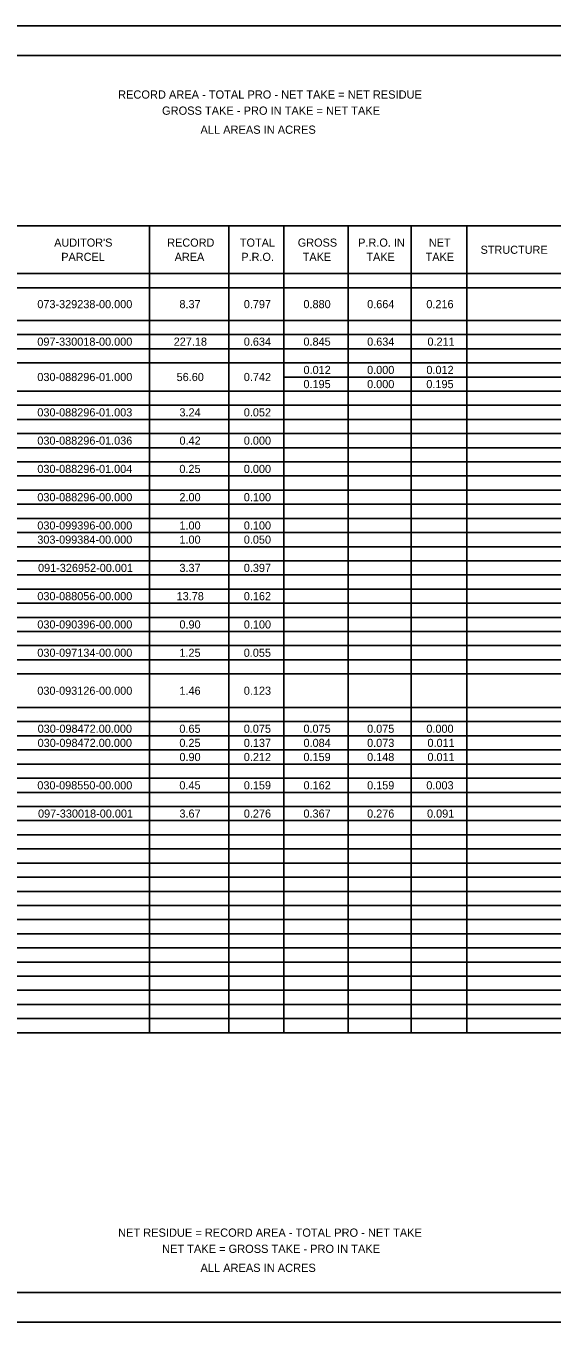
# Model space of a CAD drawing. Extents: x 0 to 38.6, y 0 to 22.
# Drawn here: x 13.07 to 22, y 0 to 22 of the extents above; entities that cross this region are included whole.
import ezdxf

# ---------------------------------------------------------------- set-up
doc = ezdxf.new("R2010")
doc.units = 0
for name, color, linetype in [('SH_Border', 7, 'Continuous'), ('SH_Cut_Line', 7, 'Continuous'), ('SH_Text', 7, 'Continuous')]:
    doc.layers.add(name, color=color, linetype=linetype)

msp = doc.modelspace()

# ---------------------------------------------------------------- linework, layer by layer
at = {"layer": 'SH_Border'}
msp.add_lwpolyline([(1.5, 21.5), (33.5, 21.5), (33.5, 0.5), (1.5, 0.5)], close=True, dxfattribs=at)
at = {"layer": 'SH_Cut_Line'}
msp.add_lwpolyline([(0, 0), (34, 0), (34, 22), (0, 22)], close=True, dxfattribs=at)
at = {"layer": 'SH_Text'}
for p, q in [((2.373, 18.606), (31.038, 18.606)), ((15.168, 18.606), (15.168, 4.911)), ((16.518, 18.606), (16.518, 4.911)), ((17.448, 18.606), (17.448, 4.911)), ((18.543, 18.606), (18.543, 4.911)), ((19.608, 18.606), (19.608, 4.911)), ((20.553, 18.606), (20.553, 4.911)), ((2.373, 17.796), (31.038, 17.796)), ((2.373, 17.556), (31.038, 17.556)), ((2.373, 17.001), (31.038, 17.001)), ((2.373, 16.761), (31.038, 16.761)), ((2.373, 16.521), (31.038, 16.521)), ((2.373, 16.281), (31.038, 16.281)), ((17.448, 16.041), (31.038, 16.041)), ((2.373, 15.801), (31.038, 15.801)), ((2.373, 15.561), (31.038, 15.561)), ((2.373, 15.321), (31.038, 15.321)), ((2.373, 15.081), (31.038, 15.081)), ((2.373, 14.841), (31.038, 14.841)), ((2.373, 14.601), (31.038, 14.601)), ((2.373, 14.361), (31.038, 14.361)), ((2.373, 14.121), (31.038, 14.121)), ((2.373, 13.881), (31.038, 13.881)), ((2.373, 13.641), (31.038, 13.641)), ((2.373, 13.401), (31.038, 13.401)), ((2.373, 13.161), (31.038, 13.161)), ((2.373, 12.921), (31.038, 12.921)), ((2.373, 12.681), (31.038, 12.681)), ((2.373, 12.441), (31.038, 12.441)), ((2.373, 12.201), (31.038, 12.201)), ((2.373, 11.961), (31.038, 11.961)), ((2.373, 11.721), (31.038, 11.721)), ((2.373, 11.481), (31.038, 11.481)), ((2.373, 11.241), (31.038, 11.241)), ((2.373, 11.001), (31.038, 11.001)), ((2.373, 10.431), (31.038, 10.431)), ((2.373, 10.191), (31.038, 10.191)), ((2.373, 9.951), (31.038, 9.951)), ((2.373, 9.711), (31.038, 9.711)), ((2.373, 9.471), (31.038, 9.471)), ((2.373, 9.231), (31.038, 9.231)), ((2.373, 8.991), (31.038, 8.991)), ((2.373, 8.751), (31.038, 8.751)), ((2.373, 8.511), (31.038, 8.511)), ((2.373, 8.271), (31.038, 8.271)), ((2.373, 8.031), (31.038, 8.031)), ((2.373, 7.791), (31.038, 7.791)), ((2.373, 7.551), (31.038, 7.551)), ((2.373, 7.311), (31.038, 7.311)), ((2.373, 7.071), (31.038, 7.071)), ((2.373, 6.831), (31.038, 6.831)), ((2.373, 6.591), (31.038, 6.591)), ((2.373, 6.351), (31.038, 6.351)), ((2.373, 6.111), (31.038, 6.111)), ((2.373, 5.871), (31.038, 5.871)), ((2.373, 5.631), (31.038, 5.631)), ((2.373, 5.391), (31.038, 5.391)), ((2.373, 5.151), (31.038, 5.151)), ((2.373, 4.911), (31.038, 4.911))]:
    msp.add_line(p, q, dxfattribs=at)

# ---------------------------------------------------------------- texts
for s, height, p in [('RECORD AREA - TOTAL PRO - NET TAKE = NET RESIDUE', 0.14, (14.637, 20.766)), ('GROSS TAKE - PRO IN TAKE = NET TAKE', 0.14, (15.383, 20.492)), ('ALL AREAS IN ACRES', 0.14, (16.035, 20.169)), ("AUDITOR'S", 0.138, (13.552, 18.253)), ('RECORD', 0.138, (15.471, 18.253)), ('TOTAL', 0.138, (16.704, 18.253)), ('GROSS', 0.138, (17.686, 18.253)), ('P.R.O. IN', 0.138, (18.711, 18.253)), ('NET', 0.138, (19.909, 18.253)), ('STRUCTURE', 0.138, (20.787, 18.132)), ('PARCEL', 0.138, (13.673, 18.011)), ('AREA', 0.138, (15.597, 18.011)), ('P.R.O.', 0.138, (16.728, 18.011)), ('TAKE', 0.138, (17.77, 18.011)), ('TAKE', 0.138, (18.85, 18.011)), ('TAKE', 0.138, (19.855, 18.011)), ('073-329238-00.000', 0.138, (13.267, 17.209)), ('8.37', 0.138, (15.678, 17.209)), ('0.797', 0.138, (16.77, 17.209)), ('0.880', 0.138, (17.782, 17.209)), ('0.664', 0.138, (18.863, 17.209)), ('0.216', 0.138, (19.867, 17.209)), ('097-330018-00.000', 0.138, (13.267, 16.572)), ('227.18', 0.138, (15.581, 16.572)), ('0.634', 0.138, (16.77, 16.572)), ('0.845', 0.138, (17.782, 16.572)), ('0.634', 0.138, (18.863, 16.572)), ('0.211', 0.138, (19.886, 16.572)), ('030-088296-01.000', 0.138, (13.267, 15.972)), ('56.60', 0.138, (15.63, 15.972)), ('0.742', 0.138, (16.77, 15.972)), ('0.012', 0.138, (17.783, 16.092)), ('0.000', 0.138, (18.862, 16.092)), ('0.012', 0.138, (19.868, 16.092)), ('0.195', 0.138, (17.782, 15.852)), ('0.000', 0.138, (18.862, 15.852)), ('0.195', 0.138, (19.867, 15.852)), ('030-088296-01.003', 0.138, (13.267, 15.372)), ('3.24', 0.138, (15.678, 15.372)), ('0.052', 0.138, (16.77, 15.372)), ('030-088296-01.036', 0.138, (13.267, 14.892)), ('0.42', 0.138, (15.679, 14.892)), ('0.000', 0.138, (16.77, 14.892)), ('030-088296-01.004', 0.138, (13.267, 14.412)), ('0.25', 0.138, (15.677, 14.412)), ('0.000', 0.138, (16.77, 14.412)), ('030-088296-00.000', 0.138, (13.267, 13.932)), ('2.00', 0.138, (15.678, 13.932)), ('0.100', 0.138, (16.77, 13.932)), ('030-099396-00.000', 0.138, (13.267, 13.452)), ('1.00', 0.138, (15.678, 13.452)), ('0.100', 0.138, (16.77, 13.452)), ('303-099384-00.000', 0.138, (13.267, 13.212)), ('1.00', 0.138, (15.678, 13.212)), ('0.050', 0.138, (16.77, 13.212)), ('091-326952-00.001', 0.138, (13.279, 12.732)), ('3.37', 0.138, (15.678, 12.732)), ('0.397', 0.138, (16.77, 12.732)), ('030-088056-00.000', 0.138, (13.267, 12.252)), ('13.78', 0.138, (15.63, 12.252)), ('0.162', 0.138, (16.77, 12.252)), ('030-090396-00.000', 0.138, (13.267, 11.772)), ('0.90', 0.138, (15.678, 11.772)), ('0.100', 0.138, (16.77, 11.772)), ('030-097134-00.000', 0.138, (13.267, 11.292)), ('1.25', 0.138, (15.677, 11.292)), ('0.055', 0.138, (16.769, 11.292)), ('030-093126-00.000', 0.138, (13.267, 10.647)), ('1.46', 0.138, (15.678, 10.647)), ('0.123', 0.138, (16.77, 10.647)), ('030-098472.00.000', 0.138, (13.272, 10.002)), ('0.65', 0.138, (15.677, 10.002)), ('0.075', 0.138, (16.769, 10.002)), ('0.075', 0.138, (17.782, 10.002)), ('0.075', 0.138, (18.862, 10.002)), ('0.000', 0.138, (19.867, 10.002)), ('030-098472.00.000', 0.138, (13.272, 9.762)), ('0.25', 0.138, (15.677, 9.762)), ('0.137', 0.138, (16.77, 9.762)), ('0.084', 0.138, (17.783, 9.762)), ('0.073', 0.138, (18.862, 9.762)), ('0.011', 0.138, (19.886, 9.762)), ('0.90', 0.138, (15.678, 9.522)), ('0.212', 0.138, (16.77, 9.522)), ('0.159', 0.138, (17.782, 9.522)), ('0.148', 0.138, (18.862, 9.522)), ('0.011', 0.138, (19.886, 9.522)), ('030-098550-00.000', 0.138, (13.267, 9.042)), ('0.45', 0.138, (15.677, 9.042)), ('0.159', 0.138, (16.77, 9.042)), ('0.162', 0.138, (17.783, 9.042)), ('0.159', 0.138, (18.862, 9.042)), ('0.003', 0.138, (19.867, 9.042)), ('097-330018-00.001', 0.138, (13.279, 8.562)), ('3.67', 0.138, (15.678, 8.562)), ('0.276', 0.138, (16.77, 8.562)), ('0.367', 0.138, (17.782, 8.562)), ('0.276', 0.138, (18.862, 8.562)), ('0.091', 0.138, (19.879, 8.562)), ('NET RESIDUE = RECORD AREA - TOTAL PRO - NET TAKE', 0.14, (14.637, 1.448)), ('NET TAKE = GROSS TAKE - PRO IN TAKE', 0.14, (15.383, 1.174)), ('ALL AREAS IN ACRES', 0.14, (16.035, 0.851))]:
    msp.add_text(s, height=height, dxfattribs=at).set_placement(p)

doc.saveas('drawing.dxf')
